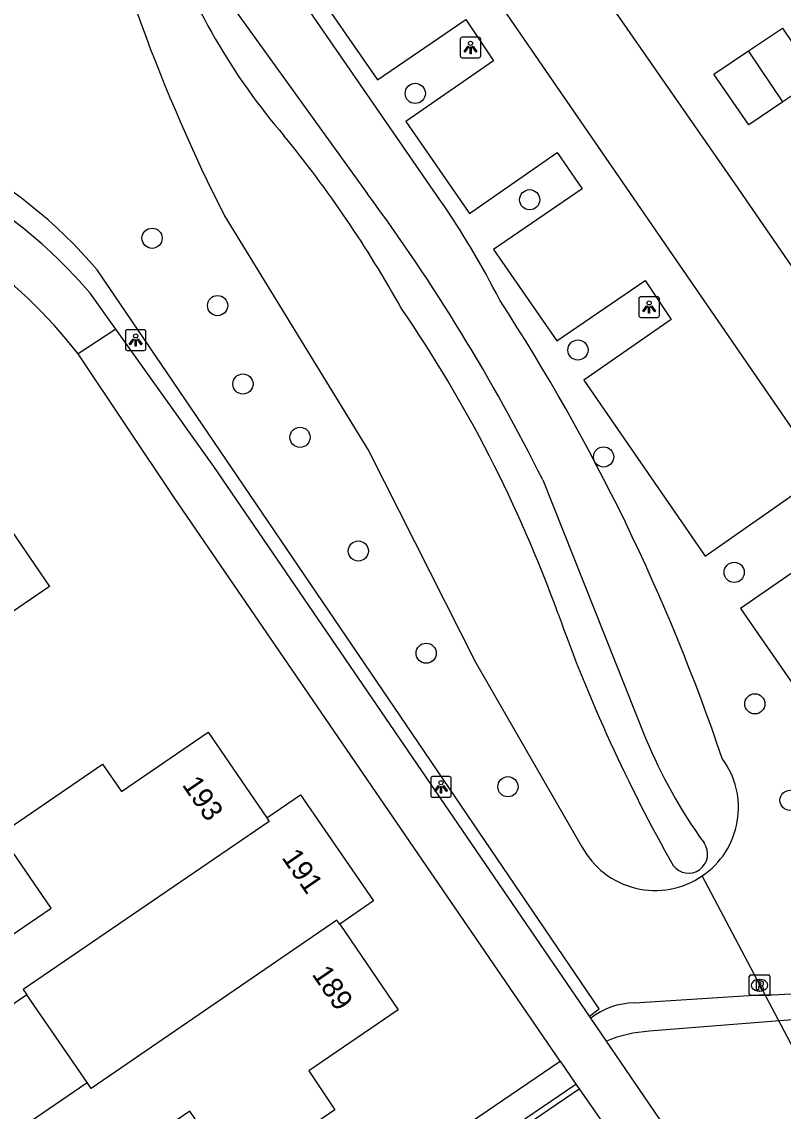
# Model space of a CAD drawing. Extents: x 155275 to 156263, y 382654 to 383635.
# Drawn here: x 155692.2 to 155729.1, y 383486.6 to 383539.4 of the extents above; entities that cross this region are included whole.
import ezdxf

# ---------------------------------------------------------------- set-up
doc = ezdxf.new("R2010")
doc.units = 0
for name, color, linetype in [('IMGEO_Boom', 7, 'Continuous'), ('IMGEO_Duiker', 7, 'Continuous'), ('IMGEO_Groenvoorziening', 7, 'Continuous'), ('IMGEO_Haag', 7, 'Continuous'), ('IMGEO_Lichtpunt', 7, 'Continuous'), ('IMGEO_Pand', 7, 'Continuous'), ('IMGEO_Pand_nummerreeks', 7, 'Continuous'), ('IMGEO_Parkeervlak_open', 7, 'Continuous'), ('IMGEO_Rijbaan_lokaal_open', 7, 'Continuous'), ('IMGEO_Rioolput', 7, 'Continuous'), ('IMGEO_Voetpad_halfverhard', 7, 'Continuous'), ('IMGEO_Voetpad_open', 7, 'Continuous'), ('IMGEO_Waterloop', 7, 'Continuous')]:
    doc.layers.add(name, color=color, linetype=linetype)

msp = doc.modelspace()

# ---------------------------------------------------------------- linework, layer by layer
at = {"layer": 'IMGEO_Boom'}
for centre in [(155711.269, 383535.951), (155716.811, 383530.8), (155698.522, 383528.934), (155701.696, 383525.67), (155719.148, 383523.52), (155702.925, 383521.874), (155705.689, 383519.291), (155720.391, 383518.34), (155708.513, 383513.783), (155726.717, 383512.748), (155711.798, 383508.831), (155727.715, 383506.378), (155715.758, 383502.364), (155729.423, 383501.706)]:
    msp.add_circle(centre, 0.489, dxfattribs=at)
at = {"layer": 'IMGEO_Duiker'}
msp.add_lwpolyline([(155730.77, 383487.457), (155725.166, 383498.045)], dxfattribs=at)
at = {"layer": 'IMGEO_Groenvoorziening'}
for points in [[(155712.463, 383530.797), (155705.532, 383540.849), (155704.449, 383542.42)], [(155702.035, 383530.021), (155709.028, 383518.625), (155714.181, 383508.401), (155719.343, 383499.458)]]:
    msp.add_lwpolyline(points, dxfattribs=at)
for centre, radius, start, end in [((155776.9, 383568.091), 83.989, 193.19206, 206.95367), ((155677.972, 383506.952), 41.931, 26.9187, 34.6581), ((155632.936, 383472.223), 98.38, 18.68144, 33.0904), ((155722.936, 383501.351), 3.988, 303.9985, 36.7113), ((155722.888, 383501.36), 4.023, 208.2225, 304.4982)]:
    msp.add_arc(centre, radius, start, end, dxfattribs=at)
at = {"layer": 'IMGEO_Haag'}
msp.add_lwpolyline([(155719.708, 383491.241), (155720.178, 383491.601), (155701.242, 383519.489), (155695.871, 383527.398)], dxfattribs=at)
msp.add_arc((155678.07, 383512.267), 23.362, 40.3649, 84.5755, dxfattribs=at)
at = {"layer": 'IMGEO_Lichtpunt'}
for p, q in [((155713.447, 383538.579), (155713.447, 383537.772)), ((155713.447, 383538.579), (155713.447, 383537.772)), ((155714.349, 383538.674), (155713.541, 383538.674)), ((155714.349, 383538.674), (155713.541, 383538.674)), ((155714.443, 383537.772), (155714.443, 383538.579)), ((155714.443, 383537.772), (155714.443, 383538.579)), ((155713.541, 383537.678), (155714.349, 383537.678)), ((155713.541, 383537.678), (155714.349, 383537.678)), ((155722.097, 383526.003), (155722.097, 383525.196)), ((155722.097, 383526.003), (155722.097, 383525.196)), ((155722.999, 383526.098), (155722.191, 383526.098)), ((155722.999, 383526.098), (155722.191, 383526.098)), ((155723.093, 383525.196), (155723.093, 383526.003)), ((155723.093, 383525.196), (155723.093, 383526.003)), ((155722.191, 383525.102), (155722.999, 383525.102)), ((155722.191, 383525.102), (155722.999, 383525.102)), ((155697.231, 383524.404), (155697.231, 383523.597)), ((155697.231, 383524.404), (155697.231, 383523.597)), ((155698.133, 383524.499), (155697.325, 383524.499)), ((155698.133, 383524.499), (155697.325, 383524.499)), ((155698.227, 383523.597), (155698.227, 383524.404)), ((155698.227, 383523.597), (155698.227, 383524.404)), ((155697.325, 383523.503), (155698.133, 383523.503)), ((155697.325, 383523.503), (155698.133, 383523.503)), ((155712.018, 383502.757), (155712.018, 383501.95)), ((155712.018, 383502.757), (155712.018, 383501.95)), ((155712.92, 383502.852), (155712.112, 383502.852)), ((155712.92, 383502.852), (155712.112, 383502.852)), ((155713.014, 383501.95), (155713.014, 383502.757)), ((155713.014, 383501.95), (155713.014, 383502.757)), ((155712.112, 383501.856), (155712.92, 383501.856)), ((155712.112, 383501.856), (155712.92, 383501.856))]:
    msp.add_line(p, q, dxfattribs=at)
for points in [[(155713.821, 383538.243), (155713.86, 383538.215), (155713.672, 383537.953), (155713.634, 383537.98), (155713.821, 383538.243)], [(155713.923, 383538.195), (155713.97, 383538.195), (155713.97, 383537.873), (155713.923, 383537.873), (155713.923, 383538.195)], [(155714.033, 383538.215), (155714.071, 383538.242), (155714.258, 383537.98), (155714.219, 383537.952), (155714.033, 383538.215)], [(155722.471, 383525.667), (155722.51, 383525.639), (155722.322, 383525.377), (155722.284, 383525.404), (155722.471, 383525.667)], [(155722.573, 383525.619), (155722.62, 383525.619), (155722.62, 383525.297), (155722.573, 383525.297), (155722.573, 383525.619)], [(155722.683, 383525.639), (155722.721, 383525.666), (155722.908, 383525.404), (155722.869, 383525.376), (155722.683, 383525.639)], [(155697.605, 383524.068), (155697.644, 383524.04), (155697.456, 383523.778), (155697.418, 383523.805), (155697.605, 383524.068)], [(155697.707, 383524.02), (155697.754, 383524.02), (155697.754, 383523.698), (155697.707, 383523.698), (155697.707, 383524.02)], [(155697.817, 383524.04), (155697.855, 383524.067), (155698.042, 383523.805), (155698.003, 383523.777), (155697.817, 383524.04)], [(155712.392, 383502.421), (155712.431, 383502.393), (155712.243, 383502.131), (155712.205, 383502.158), (155712.392, 383502.421)], [(155712.494, 383502.373), (155712.541, 383502.373), (155712.541, 383502.051), (155712.494, 383502.051), (155712.494, 383502.373)], [(155712.604, 383502.393), (155712.642, 383502.42), (155712.829, 383502.158), (155712.79, 383502.13), (155712.604, 383502.393)]]:
    msp.add_lwpolyline(points, dxfattribs=at)
for centre in [(155713.946, 383538.377), (155722.596, 383525.801), (155697.73, 383524.202), (155712.517, 383502.555)]:
    msp.add_circle(centre, 0.0994, dxfattribs=at)
for centre, start, end in [((155713.541, 383538.579), 90, 180), ((155713.541, 383538.579), 90, 180), ((155714.349, 383538.579), 0, 90), ((155714.349, 383538.579), 0, 90), ((155713.541, 383537.772), 180, 270), ((155713.541, 383537.772), 180, 270), ((155714.349, 383537.772), 270, 0), ((155714.349, 383537.772), 270, 360), ((155722.191, 383526.003), 90, 180), ((155722.191, 383526.003), 90, 180), ((155722.999, 383526.003), 0, 90), ((155722.999, 383526.003), 0, 90), ((155722.191, 383525.196), 180, 270), ((155722.191, 383525.196), 180, 270), ((155722.999, 383525.196), 270, 0), ((155722.999, 383525.196), 270, 360), ((155697.325, 383524.404), 90, 180), ((155697.325, 383524.404), 90, 180), ((155698.133, 383524.404), 0, 90), ((155698.133, 383524.404), 0, 90), ((155697.325, 383523.597), 180, 270), ((155697.325, 383523.597), 180, 270), ((155698.133, 383523.597), 270, 0), ((155698.133, 383523.597), 270, 360), ((155712.112, 383502.757), 90, 180), ((155712.112, 383502.757), 90, 180), ((155712.92, 383502.757), 0, 90), ((155712.92, 383502.757), 0, 90), ((155712.112, 383501.95), 180, 270), ((155712.112, 383501.95), 180, 270), ((155712.92, 383501.95), 270, 0), ((155712.92, 383501.95), 270, 360)]:
    msp.add_arc(centre, 0.0946, start, end, dxfattribs=at)
at = {"layer": 'IMGEO_Pand'}
for points in [[(155727.41, 383538.008), (155729.051, 383539.109), (155730.71, 383536.636), (155729.07, 383535.535)], [(155729.07, 383535.535), (155727.429, 383534.434), (155725.723, 383536.875), (155727.41, 383538.008)], [(155729.07, 383535.535), (155727.41, 383538.008)], [(155690.491, 383516.535), (155693.56, 383512.058), (155686.02, 383506.907), (155688.076, 383503.888), (155683.651, 383500.971), (155683.324, 383501.468), (155681.412, 383500.208), (155682.195, 383499.067), (155672.985, 383492.795), (155670.218, 383496.826), (155674.782, 383499.959), (155682.25, 383505.084), (155679.513, 383509.07)], [(155692.456, 383492.287), (155684.791, 383487.035), (155681.657, 383491.63), (155684.29, 383493.414), (155682.73, 383495.695), (155685.893, 383497.864), (155688.993, 383493.316), (155693.641, 383496.484), (155691.18, 383500.069), (155691.251, 383500.118), (155696.123, 383503.459), (155697.042, 383502.138), (155701.234, 383505.002), (155704.077, 383500.851)], [(155704.077, 383500.851), (155705.713, 383501.976), (155709.248, 383496.838), (155707.613, 383495.699)], [(155704.077, 383500.851), (155704.19, 383500.686), (155692.28, 383492.544), (155692.456, 383492.287)], [(155707.613, 383495.699), (155710.434, 383491.556), (155706.116, 383488.6), (155707.38, 383486.712), (155702.557, 383483.422), (155700.359, 383486.653), (155690.422, 383479.861), (155693.377, 383475.537), (155688.352, 383472.093), (155683.164, 383479.665), (155687.692, 383482.78), (155695.373, 383488.031)], [(155707.613, 383495.699), (155707.477, 383495.899), (155695.572, 383487.74), (155695.373, 383488.031)], [(155695.373, 383488.031), (155692.456, 383492.287)]]:
    msp.add_lwpolyline(points, dxfattribs=at)
at = {"layer": 'IMGEO_Parkeervlak_open'}
for points in [[(155709.684, 383548.566), (155708.198, 383547.538), (155709.364, 383545.822), (155705.101, 383542.89), (155706.233, 383541.251), (155709.44, 383536.604), (155713.711, 383539.537), (155715.066, 383537.522), (155710.807, 383534.587), (155713.891, 383530.13), (155718.142, 383533.085), (155719.35, 383531.333), (155715.062, 383528.393), (155718.123, 383523.962), (155722.4, 383526.892), (155723.669, 383524.993), (155719.432, 383522.056), (155725.308, 383513.54), (155729.557, 383516.497)], [(155731.306, 383513.946), (155727.024, 383511.005), (155732.916, 383502.493)]]:
    msp.add_lwpolyline(points, dxfattribs=at)
at = {"layer": 'IMGEO_Rijbaan_lokaal_open'}
for points in [[(155770.822, 383467.542), (155726.768, 383531.573), (155713.312, 383550.934)], [(155741.447, 383502.388), (155712.314, 383544.743), (155709.684, 383548.566)], [(155600.872, 383406.808), (155655.916, 383444.522), (155694.436, 383470.854), (155719.204, 383487.735)], [(155691.045, 383468.901), (155694.212, 383471.066), (155719.05, 383487.959)], [(155719.05, 383487.959), (155719.204, 383487.735)], [(155719.204, 383487.735), (155721.44, 383484.524)]]:
    msp.add_lwpolyline(points, dxfattribs=at)
at = {"layer": 'IMGEO_Rioolput'}
for p, q in [((155727.443, 383492.32), (155727.443, 383493.172)), ((155727.518, 383493.246), (155728.37, 383493.246)), ((155727.931, 383493.026), (155727.956, 383493.026)), ((155728.444, 383493.172), (155728.444, 383492.32)), ((155727.954, 383492.466), (155727.929, 383492.466)), ((155728.37, 383492.246), (155727.518, 383492.246))]:
    msp.add_line(p, q, dxfattribs=at)
for points in [[(155727.443, 383492.32), (155727.443, 383493.172)], [(155727.518, 383493.246), (155728.37, 383493.246)], [(155728.444, 383493.172), (155728.444, 383492.32)], [(155728.032, 383492.944), (155727.78, 383492.946), (155727.78, 383492.546)], [(155727.78, 383492.546), (155727.904, 383492.546), (155727.904, 383492.708), (155727.915, 383492.708)], [(155727.958, 383492.865), (155727.904, 383492.865), (155727.904, 383492.784)], [(155727.904, 383492.784), (155727.956, 383492.784)], [(155727.962, 383492.679), (155728.033, 383492.546), (155728.173, 383492.546), (155728.108, 383492.672)], [(155728.37, 383492.246), (155727.518, 383492.246)]]:
    msp.add_lwpolyline(points, dxfattribs=at)
for centre, radius, start, end in [((155727.52, 383493.17), 0.0765, 91.552, 178.448), ((155727.52, 383493.17), 0.0765, 91.552, 178.448), ((155728.368, 383493.17), 0.0765, 1.552, 88.448), ((155728.368, 383493.17), 0.0765, 1.552, 88.448), ((155727.914, 383492.655), 0.0533, 26.0293, 88.6989), ((155727.94, 383492.973), 0.19, 274.7715, 282.9687), ((155727.964, 383492.769), 0.0964, 77.0061, 93.1865), ((155727.978, 383492.826), 0.0378, 276.6634, 79.6772), ((155728.031, 383492.834), 0.109, 350.3612, 89.416), ((155728.029, 383492.834), 0.112, 277.5842, 350.9817), ((155728.013, 383492.619), 0.108, 29.5134, 73.7905), ((155727.52, 383492.322), 0.0765, 181.552, 268.448), ((155727.52, 383492.322), 0.0765, 181.552, 268.448), ((155728.368, 383492.322), 0.0765, 271.552, 358.448), ((155728.368, 383492.322), 0.0765, 271.552, 358.448)]:
    msp.add_arc(centre, radius, start, end, dxfattribs=at)
for centre, major_axis, ratio, start_param, end_param in [((155727.93, 383492.746), (-0.387, 0.002), 0.722429, 4.712389, 7.853982), ((155727.955, 383492.746), (-0.39, 0.002), 0.717154, 1.570796, 4.712389)]:
    msp.add_ellipse(centre, major_axis=major_axis, ratio=ratio, start_param=start_param, end_param=end_param, dxfattribs=at)
at = {"layer": 'IMGEO_Voetpad_halfverhard'}
for points in [[(155721.887, 383491.889), (155727.926, 383492.284)], [(155730.153, 383491.12), (155722.598, 383490.514)]]:
    msp.add_lwpolyline(points, dxfattribs=at)
for centre, radius, start, end in [((155728.247, 383508.029), 15.748, 268.8306, 304.8743), ((155721.914, 383488.42), 3.469, 90.4461, 128.1533), ((155722.903, 383484.505), 6.017, 92.903, 113.2037)]:
    msp.add_arc(centre, radius, start, end, dxfattribs=at)
at = {"layer": 'IMGEO_Voetpad_open'}
for points in [[(155696.77, 383524.522), (155695.524, 383526.269)], [(155696.77, 383524.522), (155694.942, 383523.334)], [(155719.708, 383491.241), (155701.514, 383517.87), (155701.108, 383518.439), (155696.77, 383524.522)], [(155718.29, 383489.069), (155700.65, 383514.84), (155699.6, 383516.374), (155694.942, 383523.334)], [(155719.771, 383491.148), (155719.708, 383491.241)], [(155720.532, 383490.035), (155719.771, 383491.148)], [(155723.759, 383485.312), (155720.532, 383490.035)], [(155689.952, 383469.783), (155694.204, 383472.684), (155718.29, 383489.069)], [(155718.29, 383489.069), (155719.05, 383487.959)]]:
    msp.add_lwpolyline(points, dxfattribs=at)
for centre, radius, start, end in [((155677.582, 383511.053), 23.525, 40.2998, 83.2429), ((155676.557, 383509.12), 23.239, 37.7086, 107.6498)]:
    msp.add_arc(centre, radius, start, end, dxfattribs=at)
at = {"layer": 'IMGEO_Waterloop'}
for points in [[(155701.981, 383540.769), (155708.944, 383531.104)], [(155717.441, 383517.232), (155722.428, 383504.723)]]:
    msp.add_lwpolyline(points, dxfattribs=at)
for centre, radius, start, end in [((155728.186, 383553.918), 30.697, 199.1312, 220.7365), ((155660.853, 383497.856), 56.926, 29.0977, 39.2653), ((155633.005, 383475.051), 94.385, 26.54502, 36.43232), ((155656.426, 383488.394), 65.681, 19.89571, 34.4395), ((155791.688, 383536.963), 78.037, 199.63058, 209.48444), ((155744.937, 383513.914), 24.313, 202.2116, 215.9511), ((155724.504, 383499.1), 0.925, 216.1925, 35.6892)]:
    msp.add_arc(centre, radius, start, end, dxfattribs=at)

# ---------------------------------------------------------------- texts
at = {"layer": 'IMGEO_Pand_nummerreeks'}
for s, rotation, p in [('193', 304.4059, (155699.949, 383502.455)), ('191', 304.5262, (155704.774, 383498.93)), ('189', 304.2512, (155706.237, 383493.278))]:
    msp.add_text(s, height=1, rotation=rotation, dxfattribs=at).set_placement(p)

doc.saveas('drawing.dxf')
